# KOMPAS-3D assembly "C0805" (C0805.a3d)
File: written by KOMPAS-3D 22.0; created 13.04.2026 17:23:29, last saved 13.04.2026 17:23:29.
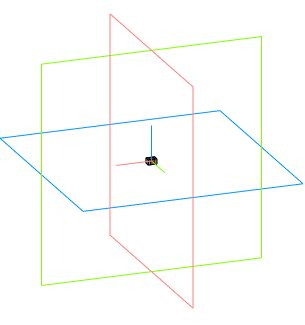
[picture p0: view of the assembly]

Document properties: Автор: Andrey; Полное имя файла: C:\Users\User1\Documents\C0805.a3d

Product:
- Component [detail]: GCJ21BR71H683KA01L  | qty 1  | source file: GCJ21BR71H683KA01L.m3d
- Part/product: C0805
    Комментарий: C0805

Referenced files in C:\Users\User1\Documents\: GCJ21BR71H683KA01L.m3d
